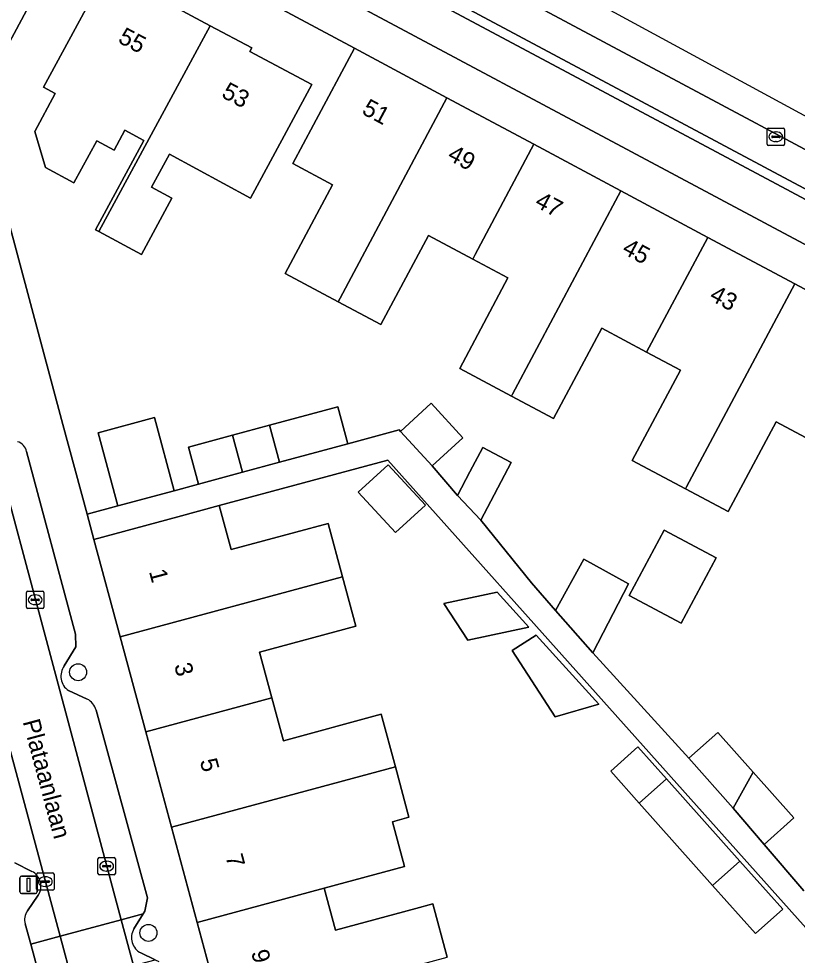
# Model space of a CAD drawing. Extents: x 159262 to 160143, y 383399 to 384319.
# Drawn here: x 159800.4 to 159845.2, y 383915.2 to 383969.1 of the extents above; entities that cross this region are included whole.
import ezdxf

# ---------------------------------------------------------------- set-up
doc = ezdxf.new("R2010")
doc.units = 0
for name, color, linetype in [('IMGEO_Boom', 7, 'Continuous'), ('IMGEO_Erf', 7, 'Continuous'), ('IMGEO_Fietspad_gesloten', 7, 'Continuous'), ('IMGEO_Kolk', 7, 'Continuous'), ('IMGEO_Lichtmast', 7, 'Continuous'), ('IMGEO_Openbare_ruimte_label', 7, 'Continuous'), ('IMGEO_Pand', 7, 'Continuous'), ('IMGEO_Pand_nummerreeks', 7, 'Continuous'), ('IMGEO_Parkeervlak_open', 7, 'Continuous'), ('IMGEO_Rijbaan_lokaal_gesloten', 7, 'Continuous'), ('IMGEO_Rijbaan_lokaal_open', 7, 'Continuous'), ('IMGEO_Verkeerseiland_open', 7, 'Continuous'), ('IMGEO_Voetpad_open', 7, 'Continuous')]:
    doc.layers.add(name, color=color, linetype=linetype)

msp = doc.modelspace()

# ---------------------------------------------------------------- linework, layer by layer
at = {"layer": 'IMGEO_Boom'}
for centre in [(159803.821, 383931.511), (159807.87, 383916.511)]:
    msp.add_circle(centre, 0.489, dxfattribs=at)
at = {"layer": 'IMGEO_Erf'}
for points in [[(159846.552, 383944.562), (159843.997, 383945.926), (159841.239, 383940.758), (159838.786, 383942.066), (159835.723, 383943.702), (159838.491, 383948.889), (159836.546, 383949.927), (159833.97, 383951.303), (159831.195, 383946.104), (159828.764, 383947.401), (159825.787, 383948.991), (159828.566, 383954.196), (159826.534, 383955.28), (159823.987, 383956.64), (159821.249, 383951.512), (159818.788, 383952.824), (159815.733, 383954.456), (159818.459, 383959.564), (159816.187, 383960.776), (159817.374, 383962.999), (159819.73, 383967.413), (159804.154, 383975.767), (159797.97, 383964.257)], [(159799.116, 383959.984), (159802.94, 383945.774), (159804.339, 383940.598), (159806.113, 383941.077), (159804.977, 383945.286), (159808.221, 383946.162), (159809.357, 383941.954), (159810.746, 383942.33), (159810.17, 383944.462), (159812.703, 383945.146), (159814.833, 383945.721), (159818.771, 383946.785), (159819.346, 383944.654), (159822.302, 383945.453), (159822.373, 383945.371), (159824.139, 383946.995), (159825.971, 383945.003), (159824.205, 383943.379), (159825.653, 383941.683), (159826.368, 383943.036), (159827.113, 383944.446), (159828.756, 383943.569), (159827.009, 383940.262), (159829.914, 383936.653), (159831.308, 383935.065), (159832.93, 383938.016), (159835.509, 383936.597), (159833.449, 383932.627), (159838.981, 383926.56), (159840.642, 383928.041), (159842.684, 383925.752), (159845.026, 383923.126), (159843.313, 383921.6), (159845.598, 383918.934)], [(159847.176, 383915.172), (159821.644, 383943.718), (159811.948, 383941.099), (159812.633, 383938.564), (159818.211, 383940.069), (159819.038, 383937.007), (159819.804, 383934.168), (159814.261, 383932.672), (159814.975, 383930.03), (159815.639, 383927.569), (159821.271, 383929.09), (159822.084, 383926.069), (159822.865, 383923.166), (159821.915, 383922.91), (159822.61, 383920.331), (159817.979, 383919.081), (159818.631, 383916.667), (159823.261, 383917.916), (159824.243, 383918.181), (159825.071, 383915.114)]]:
    msp.add_lwpolyline(points, dxfattribs=at)
for points in [[(159809.074, 383961.315), (159808.051, 383959.422), (159809.219, 383958.79), (159807.462, 383955.543), (159805.02, 383956.863), (159804.82, 383956.971), (159807.6, 383962.113), (159806.515, 383962.7), (159805.89, 383961.544), (159804.892, 383962.082), (159803.584, 383959.665), (159801.94, 383960.555), (159801.321, 383962.63), (159802.503, 383964.816), (159801.836, 383965.177), (159805.36, 383971.697), (159808.917, 383969.794), (159809.021, 383969.988), (159811.423, 383968.704), (159813.812, 383967.428), (159813.708, 383967.233), (159817.271, 383965.319), (159814.887, 383960.909), (159813.743, 383958.792)], [(159819.95, 383941.866), (159821.66, 383943.451), (159823.811, 383941.131), (159822.101, 383939.546)], [(159837.548, 383939.686), (159840.543, 383938.089), (159838.541, 383934.334), (159835.546, 383935.931)], [(159824.882, 383935.468), (159827.938, 383936.122), (159829.771, 383934.101), (159826.265, 383933.35)], [(159828.806, 383932.766), (159830.192, 383933.637), (159833.79, 383929.671), (159831.278, 383928.945)], [(159840.343, 383919.236), (159836.115, 383923.976), (159834.479, 383925.812), (159836.048, 383927.212), (159837.685, 383925.376), (159841.913, 383920.635), (159844.379, 383917.87), (159842.809, 383916.47)]]:
    msp.add_lwpolyline(points, close=True, dxfattribs=at)
at = {"layer": 'IMGEO_Fietspad_gesloten'}
msp.add_lwpolyline([(159637.547, 384066.886), (159678.317, 384045.287), (159706.724, 384030.091), (159782.916, 383989.334), (159785.314, 383988.052), (159786.588, 383987.371), (159800.678, 383979.816), (159802.382, 383978.898), (159806.209, 383976.854), (159811.759, 383973.873), (159815.384, 383972.277), (159818.103, 383970.845), (159878.488, 383938.609), (159879.571, 383940.642), (159821.924, 383971.407), (159817.239, 383973.81), (159812.887, 383975.929), (159812.762, 383975.674), (159811.755, 383976.132), (159807.769, 383978.315), (159805.944, 383979.316), (159802.985, 383980.918), (159679.545, 384046.947)], dxfattribs=at)
at = {"layer": 'IMGEO_Kolk'}
for p, q in [((159843.487, 383961.894), (159843.487, 383962.746)), ((159843.562, 383962.82), (159844.414, 383962.82)), ((159843.975, 383962.6), (159844, 383962.6)), ((159844.488, 383962.746), (159844.488, 383961.894)), ((159843.746, 383962.314), (159843.746, 383962.326)), ((159844.184, 383962.277), (159843.786, 383962.277)), ((159843.789, 383962.363), (159844.187, 383962.363)), ((159843.998, 383962.04), (159843.973, 383962.04)), ((159844.23, 383962.326), (159844.23, 383962.314)), ((159844.414, 383961.82), (159843.562, 383961.82)), ((159800.847, 383935.253), (159800.847, 383936.105)), ((159800.922, 383936.179), (159801.774, 383936.179)), ((159801.848, 383936.105), (159801.848, 383935.253)), ((159801.106, 383935.673), (159801.106, 383935.685)), ((159801.544, 383935.636), (159801.146, 383935.636)), ((159801.149, 383935.722), (159801.547, 383935.722)), ((159801.335, 383935.959), (159801.36, 383935.959)), ((159801.59, 383935.685), (159801.59, 383935.673)), ((159801.774, 383935.179), (159800.922, 383935.179)), ((159801.358, 383935.399), (159801.333, 383935.399)), ((159804.965, 383919.927), (159804.965, 383920.779)), ((159805.04, 383920.853), (159805.892, 383920.853)), ((159805.453, 383920.633), (159805.478, 383920.633)), ((159805.966, 383920.779), (159805.966, 383919.927)), ((159801.507, 383919.963), (159802.359, 383919.963)), ((159805.224, 383920.347), (159805.224, 383920.359)), ((159805.662, 383920.31), (159805.264, 383920.31)), ((159805.267, 383920.396), (159805.665, 383920.396)), ((159805.476, 383920.073), (159805.451, 383920.073)), ((159805.708, 383920.359), (159805.708, 383920.347)), ((159801.432, 383919.037), (159801.432, 383919.889)), ((159801.691, 383919.457), (159801.691, 383919.469)), ((159802.129, 383919.42), (159801.731, 383919.42)), ((159801.734, 383919.506), (159802.132, 383919.506)), ((159801.92, 383919.743), (159801.945, 383919.743)), ((159802.175, 383919.469), (159802.175, 383919.457)), ((159802.433, 383919.889), (159802.433, 383919.037)), ((159805.892, 383919.853), (159805.04, 383919.853)), ((159802.359, 383918.963), (159801.507, 383918.963)), ((159801.943, 383919.183), (159801.918, 383919.183))]:
    msp.add_line(p, q, dxfattribs=at)
for points in [[(159843.487, 383961.894), (159843.487, 383962.746)], [(159843.562, 383962.82), (159844.414, 383962.82)], [(159844.488, 383962.746), (159844.488, 383961.894)], [(159844.414, 383961.82), (159843.562, 383961.82)], [(159800.847, 383935.253), (159800.847, 383936.105)], [(159800.922, 383936.179), (159801.774, 383936.179)], [(159801.848, 383936.105), (159801.848, 383935.253)], [(159801.774, 383935.179), (159800.922, 383935.179)], [(159804.965, 383919.927), (159804.965, 383920.779)], [(159805.04, 383920.853), (159805.892, 383920.853)], [(159805.966, 383920.779), (159805.966, 383919.927)], [(159801.507, 383919.963), (159802.359, 383919.963)], [(159801.432, 383919.037), (159801.432, 383919.889)], [(159802.433, 383919.889), (159802.433, 383919.037)], [(159805.892, 383919.853), (159805.04, 383919.853)], [(159802.359, 383918.963), (159801.507, 383918.963)]]:
    msp.add_lwpolyline(points, dxfattribs=at)
for centre, radius, start, end in [((159843.564, 383962.744), 0.0765, 91.552, 178.448), ((159843.564, 383962.744), 0.0765, 91.552, 178.448), ((159844.412, 383962.744), 0.0765, 1.552, 88.448), ((159844.412, 383962.744), 0.0765, 1.552, 88.448), ((159843.786, 383962.323), 0.0403, 85.8775, 175.7526), ((159843.783, 383962.313), 0.0366, 178.938, 274.7102), ((159844.187, 383962.32), 0.043, 264.8664, 352.4533), ((159844.191, 383962.325), 0.0386, 1.7309, 96.639), ((159843.564, 383961.896), 0.0765, 181.552, 268.448), ((159843.564, 383961.896), 0.0765, 181.552, 268.448), ((159844.412, 383961.896), 0.0765, 271.552, 358.448), ((159844.412, 383961.896), 0.0765, 271.552, 358.448), ((159800.924, 383936.103), 0.0765, 91.552, 178.448), ((159800.924, 383936.103), 0.0765, 91.552, 178.448), ((159801.772, 383936.103), 0.0765, 1.552, 88.448), ((159801.772, 383936.103), 0.0765, 1.552, 88.448), ((159801.146, 383935.682), 0.0403, 85.8775, 175.7526), ((159801.143, 383935.672), 0.0366, 178.938, 274.7102), ((159801.547, 383935.679), 0.043, 264.8664, 352.4533), ((159801.551, 383935.684), 0.0386, 1.7309, 96.639), ((159800.924, 383935.255), 0.0765, 181.552, 268.448), ((159800.924, 383935.255), 0.0765, 181.552, 268.448), ((159801.772, 383935.255), 0.0765, 271.552, 358.448), ((159801.772, 383935.255), 0.0765, 271.552, 358.448), ((159805.042, 383920.777), 0.0765, 91.552, 178.448), ((159805.042, 383920.777), 0.0765, 91.552, 178.448), ((159805.89, 383920.777), 0.0765, 1.552, 88.448), ((159805.89, 383920.777), 0.0765, 1.552, 88.448), ((159801.509, 383919.887), 0.0765, 91.552, 178.448), ((159801.509, 383919.887), 0.0765, 91.552, 178.448), ((159802.357, 383919.887), 0.0765, 1.552, 88.448), ((159802.357, 383919.887), 0.0765, 1.552, 88.448), ((159805.042, 383919.929), 0.0765, 181.552, 268.448), ((159805.042, 383919.929), 0.0765, 181.552, 268.448), ((159805.264, 383920.356), 0.0403, 85.8775, 175.7526), ((159805.261, 383920.346), 0.0366, 178.938, 274.7102), ((159805.665, 383920.353), 0.043, 264.8664, 352.4533), ((159805.669, 383920.358), 0.0386, 1.7309, 96.639), ((159805.89, 383919.929), 0.0765, 271.552, 358.448), ((159805.89, 383919.929), 0.0765, 271.552, 358.448), ((159801.731, 383919.466), 0.0403, 85.8775, 175.7526), ((159801.728, 383919.456), 0.0366, 178.938, 274.7102), ((159802.132, 383919.463), 0.043, 264.8664, 352.4533), ((159802.136, 383919.468), 0.0386, 1.7309, 96.639), ((159801.509, 383919.039), 0.0765, 181.552, 268.448), ((159801.509, 383919.039), 0.0765, 181.552, 268.448), ((159802.357, 383919.039), 0.0765, 271.552, 358.448), ((159802.357, 383919.039), 0.0765, 271.552, 358.448)]:
    msp.add_arc(centre, radius, start, end, dxfattribs=at)
for centre, major_axis, ratio, start_param, end_param in [((159843.974, 383962.32), (-0.387, 0.002), 0.722429, 4.712389, 7.853982), ((159843.999, 383962.32), (-0.39, 0.002), 0.717154, 1.570796, 4.712389), ((159801.334, 383935.679), (-0.387, 0.002), 0.722429, 4.712389, 7.853982), ((159801.359, 383935.679), (-0.39, 0.002), 0.717154, 1.570796, 4.712389), ((159805.452, 383920.353), (-0.387, 0.002), 0.722429, 4.712389, 7.853982), ((159805.477, 383920.353), (-0.39, 0.002), 0.717154, 1.570796, 4.712389), ((159801.919, 383919.463), (-0.387, 0.002), 0.722429, 4.712389, 7.853982), ((159801.944, 383919.463), (-0.39, 0.002), 0.717154, 1.570796, 4.712389)]:
    msp.add_ellipse(centre, major_axis=major_axis, ratio=ratio, start_param=start_param, end_param=end_param, dxfattribs=at)
at = {"layer": 'IMGEO_Lichtmast'}
for p, q in [((159800.469, 383918.879), (159800.469, 383919.679)), ((159800.469, 383919.679), (159800.469, 383918.879)), ((159800.569, 383919.779), (159801.359, 383919.779)), ((159801.359, 383919.779), (159800.569, 383919.779)), ((159801.459, 383919.679), (159801.459, 383918.879)), ((159801.459, 383918.879), (159801.459, 383919.679)), ((159801.359, 383918.779), (159800.569, 383918.779)), ((159800.569, 383918.779), (159801.359, 383918.779))]:
    msp.add_line(p, q, dxfattribs=at)
msp.add_lwpolyline([(159800.889, 383919.654), (159801.039, 383919.654), (159801.039, 383918.904), (159800.889, 383918.904), (159800.889, 383919.654)], dxfattribs=at)
for centre, start, end in [((159800.569, 383919.679), 90, 180), ((159800.569, 383919.679), 90, 180), ((159801.359, 383919.679), 0, 90), ((159801.359, 383919.679), 360, 90), ((159800.569, 383918.879), 180, 270), ((159800.569, 383918.879), 180, 270), ((159801.359, 383918.879), 270, 0), ((159801.359, 383918.879), 270, 0)]:
    msp.add_arc(centre, 0.1, start, end, dxfattribs=at)
at = {"layer": 'IMGEO_Pand'}
for points in [[(159811.423, 383968.704), (159809.021, 383969.988), (159808.917, 383969.794), (159805.36, 383971.697), (159801.836, 383965.177), (159802.503, 383964.816), (159801.321, 383962.63), (159801.94, 383960.555), (159803.584, 383959.665), (159804.892, 383962.082), (159805.89, 383961.544), (159806.515, 383962.7), (159807.6, 383962.113), (159804.82, 383956.971), (159805.02, 383956.863)], [(159817.271, 383965.319), (159813.708, 383967.233), (159813.812, 383967.428), (159811.423, 383968.704), (159805.02, 383956.863), (159807.462, 383955.543), (159809.219, 383958.79), (159808.051, 383959.422), (159809.074, 383961.315), (159813.743, 383958.792), (159814.887, 383960.909)], [(159825.054, 383964.564), (159819.73, 383967.413), (159817.374, 383962.999), (159816.187, 383960.776), (159818.459, 383959.564), (159815.733, 383954.456), (159818.788, 383952.824), (159818.898, 383953.031)], [(159830.059, 383961.885), (159825.054, 383964.564), (159818.898, 383953.031), (159818.788, 383952.824), (159821.249, 383951.512), (159823.987, 383956.64), (159826.534, 383955.28), (159826.68, 383955.554)], [(159835.066, 383959.206), (159830.059, 383961.885), (159826.68, 383955.554), (159826.534, 383955.28), (159828.566, 383954.196), (159825.787, 383948.991), (159828.764, 383947.401), (159828.819, 383947.504)], [(159840.07, 383956.528), (159835.066, 383959.206), (159828.819, 383947.504), (159828.764, 383947.401), (159831.195, 383946.104), (159833.97, 383951.303), (159836.546, 383949.927)], [(159845.075, 383953.849), (159840.07, 383956.528), (159836.546, 383949.927), (159838.491, 383948.889), (159835.723, 383943.702), (159838.786, 383942.066), (159838.844, 383942.177)], [(159850.08, 383951.17), (159845.075, 383953.849), (159838.844, 383942.177), (159838.786, 383942.066), (159841.239, 383940.758), (159843.997, 383945.926), (159846.552, 383944.562)], [(159822.373, 383945.371), (159824.205, 383943.379), (159825.971, 383945.003), (159824.139, 383946.995)], [(159814.833, 383945.721), (159815.409, 383943.59), (159819.346, 383944.654), (159818.771, 383946.785)], [(159804.977, 383945.286), (159806.113, 383941.077), (159809.357, 383941.954), (159808.221, 383946.162)], [(159814.833, 383945.721), (159812.703, 383945.146), (159813.279, 383943.014), (159815.409, 383943.59)], [(159812.703, 383945.146), (159810.17, 383944.462), (159810.746, 383942.33), (159813.279, 383943.014)], [(159828.756, 383943.569), (159827.113, 383944.446), (159826.368, 383943.036), (159825.653, 383941.683), (159827.009, 383940.262)], [(159819.95, 383941.866), (159822.101, 383939.546), (159823.811, 383941.131), (159821.66, 383943.451)], [(159818.211, 383940.069), (159812.633, 383938.564), (159811.948, 383941.099), (159809.567, 383940.456), (159804.73, 383939.15), (159806.241, 383933.553), (159819.038, 383937.007)], [(159835.546, 383935.931), (159838.541, 383934.334), (159840.543, 383938.089), (159837.548, 383939.686)], [(159835.509, 383936.597), (159832.93, 383938.016), (159831.308, 383935.065), (159833.449, 383932.627)], [(159814.261, 383932.672), (159819.804, 383934.168), (159819.038, 383937.007), (159806.241, 383933.553), (159807.721, 383928.073), (159814.975, 383930.03)], [(159824.882, 383935.468), (159826.265, 383933.35), (159829.771, 383934.101), (159827.938, 383936.122)], [(159830.192, 383933.637), (159828.806, 383932.766), (159831.278, 383928.945), (159833.79, 383929.671)], [(159821.271, 383929.09), (159815.639, 383927.569), (159814.975, 383930.03), (159807.721, 383928.073), (159809.201, 383922.592), (159822.084, 383926.069)], [(159838.981, 383926.56), (159841.529, 383923.681), (159842.684, 383925.752), (159840.642, 383928.041)], [(159836.115, 383923.976), (159837.685, 383925.376), (159836.048, 383927.212), (159834.479, 383925.812)], [(159821.915, 383922.91), (159822.865, 383923.166), (159822.084, 383926.069), (159809.201, 383922.592), (159810.681, 383917.11), (159817.979, 383919.081), (159822.61, 383920.331)], [(159837.685, 383925.376), (159836.115, 383923.976), (159840.343, 383919.236), (159841.913, 383920.635)], [(159842.684, 383925.752), (159841.529, 383923.681), (159843.313, 383921.6), (159845.026, 383923.126)], [(159841.913, 383920.635), (159840.343, 383919.236), (159842.809, 383916.47), (159844.379, 383917.87)], [(159824.243, 383918.181), (159823.261, 383917.916), (159818.631, 383916.667), (159817.979, 383919.081), (159810.681, 383917.11), (159812.161, 383911.63), (159825.071, 383915.114)]]:
    msp.add_lwpolyline(points, close=True, dxfattribs=at)
at = {"layer": 'IMGEO_Parkeervlak_open'}
for points in [[(159889.226, 383938.344), (159827.568, 383971.273), (159818.616, 383975.911), (159814.9, 383977.723), (159810.574, 383979.653)], [(159813.13, 383976.392), (159822.09, 383971.919), (159885.523, 383938.052)], [(159794.586, 383960.962), (159806.295, 383917.265), (159807.559, 383917.606), (159807.653, 383917.76), (159807.814, 383918.54), (159804.851, 383929.32)], [(159800.777, 383917.037), (159801.092, 383915.863), (159802.78, 383916.318), (159791.028, 383959.973)], [(159803.023, 383931.877), (159803.688, 383932.969), (159803.663, 383933.697), (159800.853, 383944.204)], [(159804.335, 383929.97), (159803.261, 383930.453)], [(159800.184, 383920.549), (159801.155, 383920.054)], [(159801.53, 383918.676), (159800.907, 383917.786)], [(159807.032, 383916.742), (159807.559, 383917.606), (159806.295, 383917.265), (159807.004, 383914.628), (159808.261, 383914.967), (159807.438, 383915.357)]]:
    msp.add_lwpolyline(points, dxfattribs=at)
msp.add_lwpolyline([(159801.092, 383915.863), (159801.8, 383913.227), (159803.49, 383913.682), (159802.78, 383916.318)], close=True, dxfattribs=at)
for centre, radius, start, end in [((159800.161, 383944.094), 0.701, 9.0228, 75.6047), ((159803.854, 383931.284), 1.021, 144.4842, 234.4926), ((159803.883, 383929.081), 0.997, 13.857, 63.0313), ((159800.73, 383919.198), 0.955, 326.8519, 63.595), ((159801.549, 383917.289), 0.812, 142.2437, 198.0634), ((159807.871, 383916.236), 0.98, 148.9217, 243.7544)]:
    msp.add_arc(centre, radius, start, end, dxfattribs=at)
at = {"layer": 'IMGEO_Rijbaan_lokaal_gesloten'}
msp.add_lwpolyline([(159892.323, 383938.219), (159805.451, 383985.323), (159805.451, 383985.323), (159804.103, 383983.128), (159807.258, 383981.498), (159808.939, 383980.578), (159810.574, 383979.653), (159814.9, 383977.723), (159818.616, 383975.911), (159827.568, 383971.273), (159889.226, 383938.344), (159891.696, 383937.001), (159892.323, 383938.219)], dxfattribs=at)
at = {"layer": 'IMGEO_Rijbaan_lokaal_open'}
for points in [[(159791.028, 383959.973), (159802.78, 383916.318), (159806.295, 383917.265), (159794.586, 383960.962)], [(159803.49, 383913.682), (159807.004, 383914.628), (159806.295, 383917.265), (159802.78, 383916.318)]]:
    msp.add_lwpolyline(points, close=True, dxfattribs=at)
at = {"layer": 'IMGEO_Verkeerseiland_open'}
for points in [[(159807.769, 383978.315), (159811.755, 383976.132), (159812.762, 383975.674), (159812.887, 383975.929), (159817.239, 383973.81), (159821.924, 383971.407), (159879.571, 383940.642), (159890.781, 383934.659), (159891.232, 383935.057), (159891.895, 383936.33)], [(159885.523, 383938.052), (159822.09, 383971.919), (159813.13, 383976.392)]]:
    msp.add_lwpolyline(points, dxfattribs=at)
at = {"layer": 'IMGEO_Voetpad_open'}
for points in [[(159773.286, 383964.712), (159777.272, 383965.773), (159786.462, 383960.973), (159787.021, 383958.859), (159791.028, 383959.973), (159794.586, 383960.962), (159798.558, 383962.066), (159797.97, 383964.257), (159804.154, 383975.767), (159801.504, 383977.274), (159797.975, 383970.745), (159796.283, 383971.71), (159799.849, 383978.287), (159798.435, 383979.068), (159793.382, 383969.546), (159781.4, 383976.131), (159786.364, 383985.485), (159784.475, 383986.467), (159780.906, 383979.79), (159779.155, 383980.75), (159782.751, 383987.322), (159780.198, 383988.588), (159774.115, 383977.461)], [(159961.003, 383894.56), (159878.488, 383938.609), (159818.103, 383970.845), (159815.384, 383972.277), (159811.759, 383973.873), (159806.209, 383976.854), (159802.382, 383978.898), (159801.504, 383977.274), (159804.154, 383975.767), (159819.73, 383967.413), (159825.054, 383964.564), (159830.059, 383961.885), (159835.066, 383959.206), (159840.07, 383956.528), (159845.075, 383953.849), (159850.08, 383951.17), (159855.086, 383948.492), (159859.986, 383945.869), (159861.023, 383945.315), (159891.308, 383929.133), (159892.341, 383928.581), (159922.62, 383912.402)], [(159809.201, 383922.592), (159807.721, 383928.073), (159806.241, 383933.553), (159804.73, 383939.15), (159804.339, 383940.598), (159802.94, 383945.774), (159799.116, 383959.984), (159798.558, 383962.066), (159794.586, 383960.962)], [(159845.598, 383918.934), (159843.313, 383921.6), (159841.529, 383923.681), (159838.981, 383926.56), (159833.449, 383932.627), (159831.308, 383935.065), (159829.914, 383936.653), (159827.009, 383940.262), (159825.653, 383941.683), (159824.205, 383943.379), (159822.373, 383945.371), (159822.302, 383945.453), (159819.346, 383944.654), (159815.409, 383943.59), (159813.279, 383943.014), (159810.746, 383942.33), (159809.357, 383941.954), (159806.113, 383941.077), (159804.339, 383940.598), (159804.73, 383939.15), (159809.567, 383940.456), (159811.948, 383941.099), (159821.644, 383943.718), (159847.176, 383915.172)], [(159800.853, 383944.204), (159803.663, 383933.697), (159803.688, 383932.969), (159803.023, 383931.877)], [(159803.261, 383930.453), (159804.335, 383929.97)], [(159804.851, 383929.32), (159807.814, 383918.54), (159807.653, 383917.76), (159807.559, 383917.606), (159807.032, 383916.742)], [(159825.103, 383863.552), (159823.801, 383868.486), (159817.022, 383893.625), (159816.632, 383895.071), (159815.121, 383900.668), (159813.641, 383906.148), (159812.161, 383911.63), (159810.681, 383917.11), (159809.201, 383922.592)], [(159801.155, 383920.054), (159800.184, 383920.549)], [(159800.907, 383917.786), (159801.53, 383918.676)], [(159804.889, 383901.725), (159801.8, 383913.227), (159801.092, 383915.863), (159800.777, 383917.037)], [(159807.438, 383915.357), (159808.261, 383914.967), (159808.459, 383914.873)]]:
    msp.add_lwpolyline(points, dxfattribs=at)
for centre, radius, start, end in [((159800.161, 383944.094), 0.701, 9.0228, 75.6047), ((159803.854, 383931.284), 1.021, 144.4842, 234.4926), ((159803.883, 383929.081), 0.997, 13.857, 63.0313), ((159800.73, 383919.198), 0.955, 326.8519, 63.595), ((159801.549, 383917.289), 0.812, 142.2437, 198.0634), ((159807.871, 383916.236), 0.98, 148.9217, 243.7544)]:
    msp.add_arc(centre, radius, start, end, dxfattribs=at)

# ---------------------------------------------------------------- texts
at = {"layer": 'IMGEO_Openbare_ruimte_label'}
msp.add_text('Plataanlaan', height=1, rotation=285.0089, dxfattribs=at).set_placement((159800.623, 383928.67))
at = {"layer": 'IMGEO_Pand_nummerreeks'}
for s, rotation, p in [('55', 332.1256, (159806.06, 383967.779)), ('53', 332.1256, (159812.015, 383964.629)), ('51', 331.8334, (159820.094, 383963.673)), ('49', 331.8334, (159825.021, 383961.035)), ('47', 331.8334, (159830.049, 383958.343)), ('45', 331.8334, (159835.076, 383955.651)), ('43', 331.8334, (159840.104, 383952.959)), ('1', 285.0285, (159807.895, 383937.308)), ('3', 285.0285, (159809.342, 383931.915)), ('5', 285.0285, (159810.819, 383926.413)), ('7', 285.0285, (159812.296, 383920.911)), ('9', 285.0285, (159813.773, 383915.409))]:
    msp.add_text(s, height=1, rotation=rotation, dxfattribs=at).set_placement(p)

doc.saveas('drawing.dxf')
